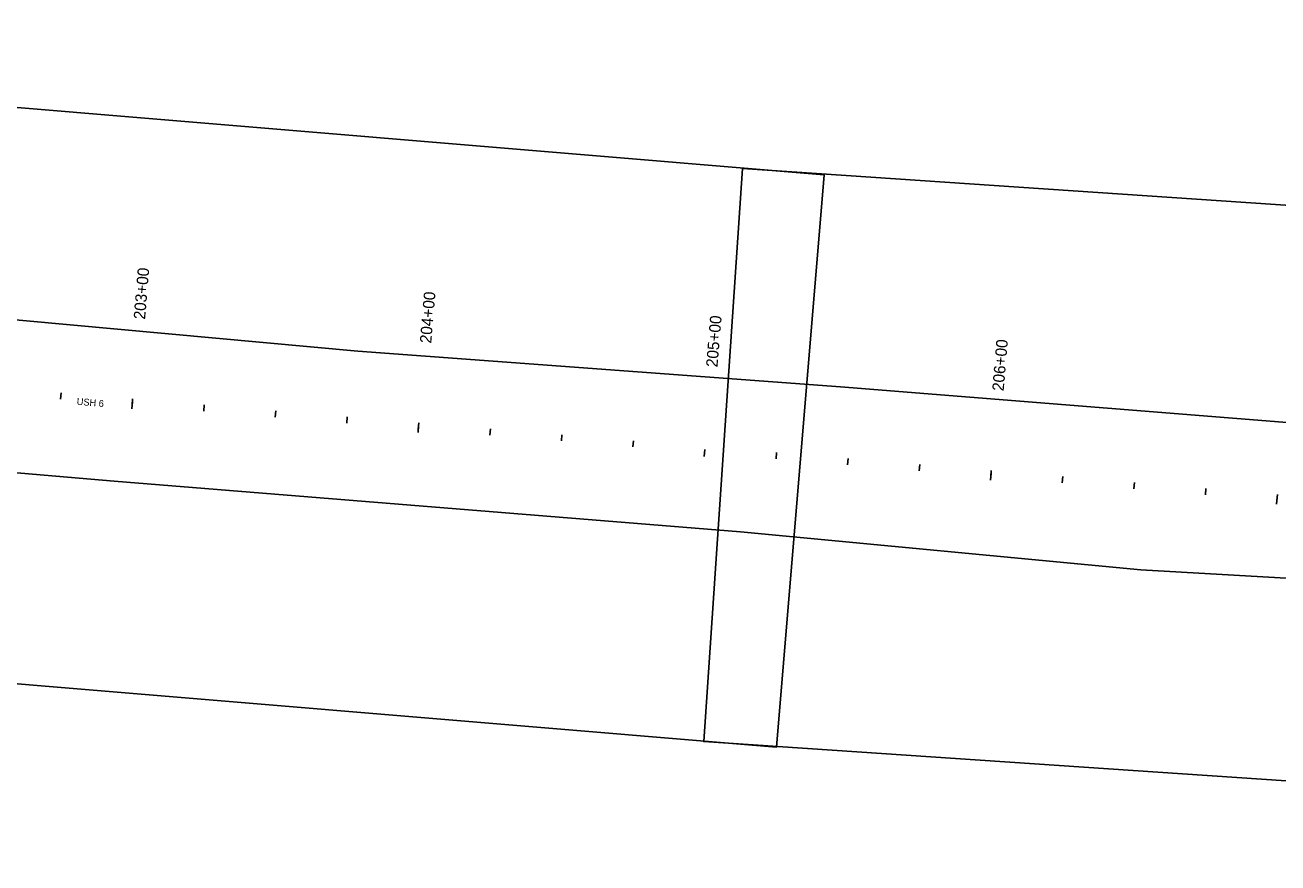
# Model space of a CAD drawing. Extents: x 20499876 to 20505320, y 7953544 to 7954108.
# Drawn here: x 20503963.1 to 20504399.3, y 7953543.8 to 7953835.6 of the extents above; entities that cross this region are included whole.
import ezdxf

# ---------------------------------------------------------------- set-up
doc = ezdxf.new("R2010")
doc.units = 0
for name, color, linetype in [('Alignment', 7, 'Continuous'), ('Curb', 7, 'Continuous'), ('Draft_0', 7, 'Continuous'), ('Draft_7', 7, 'Continuous'), ('UtilitiesBelowGround', 7, 'Continuous')]:
    doc.layers.add(name, color=color, linetype=linetype)

msp = doc.modelspace()

# ---------------------------------------------------------------- linework, layer by layer
at = {"layer": 'Alignment'}
for points in [[(20503616.55, 7953835.62), (20503599.92, 7953636.31), (20504224.75, 7953584.17), (20504241.38, 7953783.48)], [(20504212.89, 7953785.63), (20504199.4, 7953586.08), (20504824.91, 7953543.82), (20504838.4, 7953743.37)]]:
    msp.add_lwpolyline(points, close=True, dxfattribs=at)
at = {"layer": 'Curb'}
for p, q in [((20504000.37, 7953703.24), (20504000.56, 7953705.42)), ((20504100.03, 7953694.92), (20504100.21, 7953697.1)), ((20504199.78, 7953687.83), (20504199.58, 7953685.39)), ((20504299.33, 7953678.29), (20504299.52, 7953680.47)), ((20504398.99, 7953669.98), (20504399.17, 7953672.16))]:
    msp.add_line(p, q, dxfattribs=at)
at = {"layer": 'Draft_7'}
for p, q in [((20503975.46, 7953705.32), (20503975.64, 7953707.5)), ((20504000.48, 7953704.46), (20504000.27, 7953702.02)), ((20504025.29, 7953701.16), (20504025.47, 7953703.34)), ((20504050.2, 7953699.08), (20504050.38, 7953701.26)), ((20504075.11, 7953697), (20504075.3, 7953699.18)), ((20504100.13, 7953696.14), (20504099.93, 7953693.7)), ((20504124.94, 7953692.85), (20504125.12, 7953695.02)), ((20504149.85, 7953690.77), (20504150.04, 7953692.94)), ((20504174.77, 7953688.69), (20504174.95, 7953690.86)), ((20504199.78, 7953687.83), (20504199.58, 7953685.39)), ((20504224.59, 7953684.53), (20504224.78, 7953686.71)), ((20504249.51, 7953682.45), (20504249.69, 7953684.63)), ((20504274.42, 7953680.37), (20504274.6, 7953682.55)), ((20504299.44, 7953679.51), (20504299.23, 7953677.07)), ((20504324.25, 7953676.21), (20504324.43, 7953678.39)), ((20504349.16, 7953674.14), (20504349.34, 7953676.31)), ((20504374.08, 7953672.06), (20504374.26, 7953674.23)), ((20504399.09, 7953671.2), (20504398.89, 7953668.76))]:
    msp.add_line(p, q, dxfattribs=at)
at = {"layer": 'UtilitiesBelowGround'}
msp.add_lwpolyline([(20503829.09, 7953744.97), (20504079.02, 7953722.08), (20504247.03, 7953709.66), (20504477.95, 7953691.2), (20504693.1, 7953690.35), (20504707.3, 7953684.41), (20504703.39, 7953615.5), (20504682.83, 7953610.75), (20504591.14, 7953627.72), (20504566.72, 7953585.85), (20504541.05, 7953588.36), (20504519.52, 7953636.21), (20504351.61, 7953645.9), (20504212.21, 7953659.14), (20503994.1, 7953676.75), (20503832.88, 7953690.55)], dxfattribs=at)

# ---------------------------------------------------------------- texts
at = {"layer": 'Curb'}
msp.add_text('205+00', height=4.008, rotation=85.2296, dxfattribs=at).set_placement((20504204.17, 7953716.34))
at = {"layer": 'Draft_0'}
msp.add_text('USH 6', height=2.4, rotation=355, dxfattribs=at).set_placement((20503981.01, 7953703.39))
at = {"layer": 'Draft_7'}
for s, rotation, p in [('203+00', 85.2296, (20504004.87, 7953732.97)), ('204+00', 85.2296, (20504104.52, 7953724.65)), ('205+00', 85.2296, (20504204.17, 7953716.34)), ('206+00', 85.2308, (20504303.83, 7953708.02))]:
    msp.add_text(s, height=4.008, rotation=rotation, dxfattribs=at).set_placement(p)

doc.saveas('drawing.dxf')
